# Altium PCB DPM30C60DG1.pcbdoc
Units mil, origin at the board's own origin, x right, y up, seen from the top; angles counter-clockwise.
Board outline 2020 x 1717.48 mil, 2 copper layers (Top Layer, Bottom Layer), stack 0 mil thick; 1 components, 0 nets, 24 pads, 0 vias.
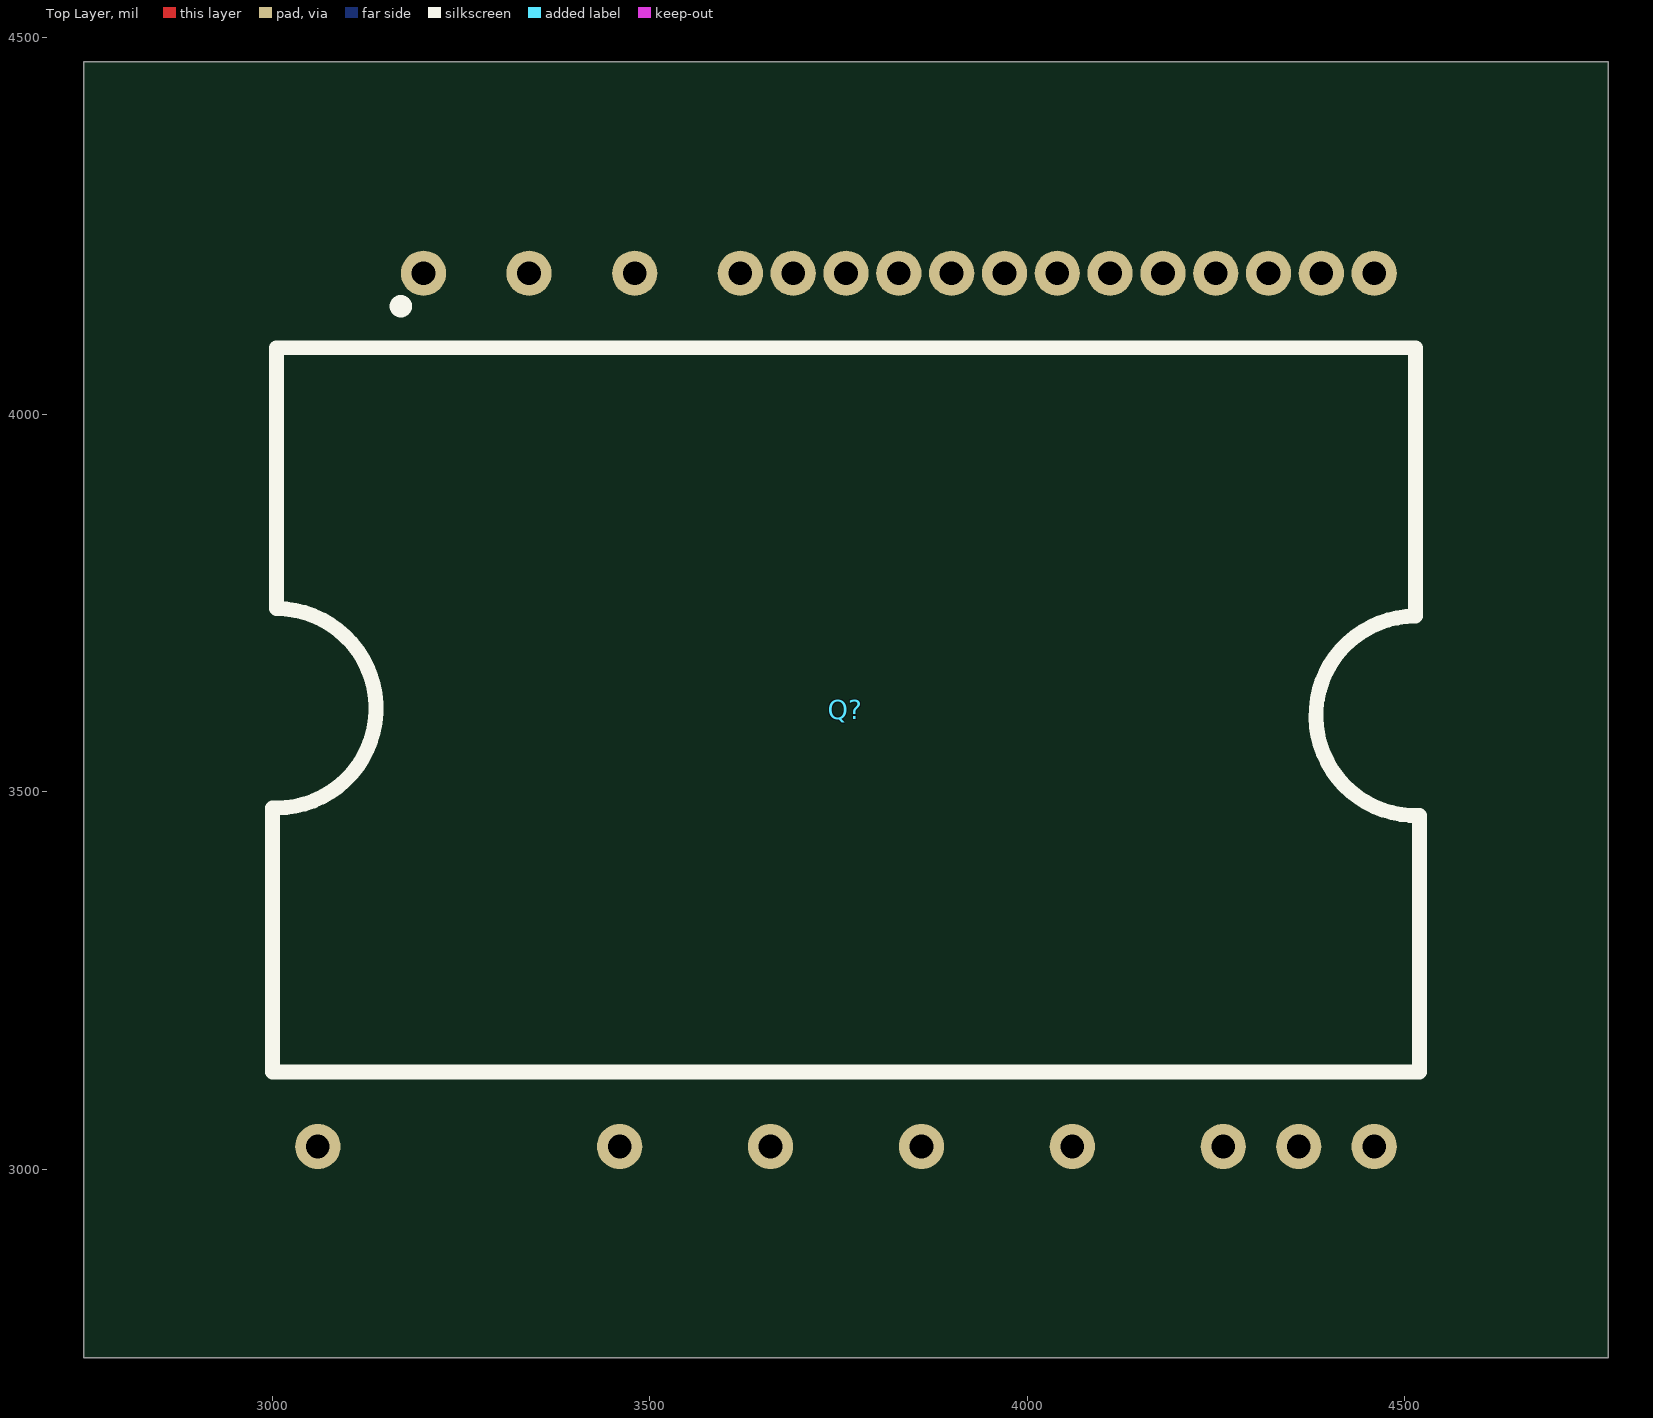
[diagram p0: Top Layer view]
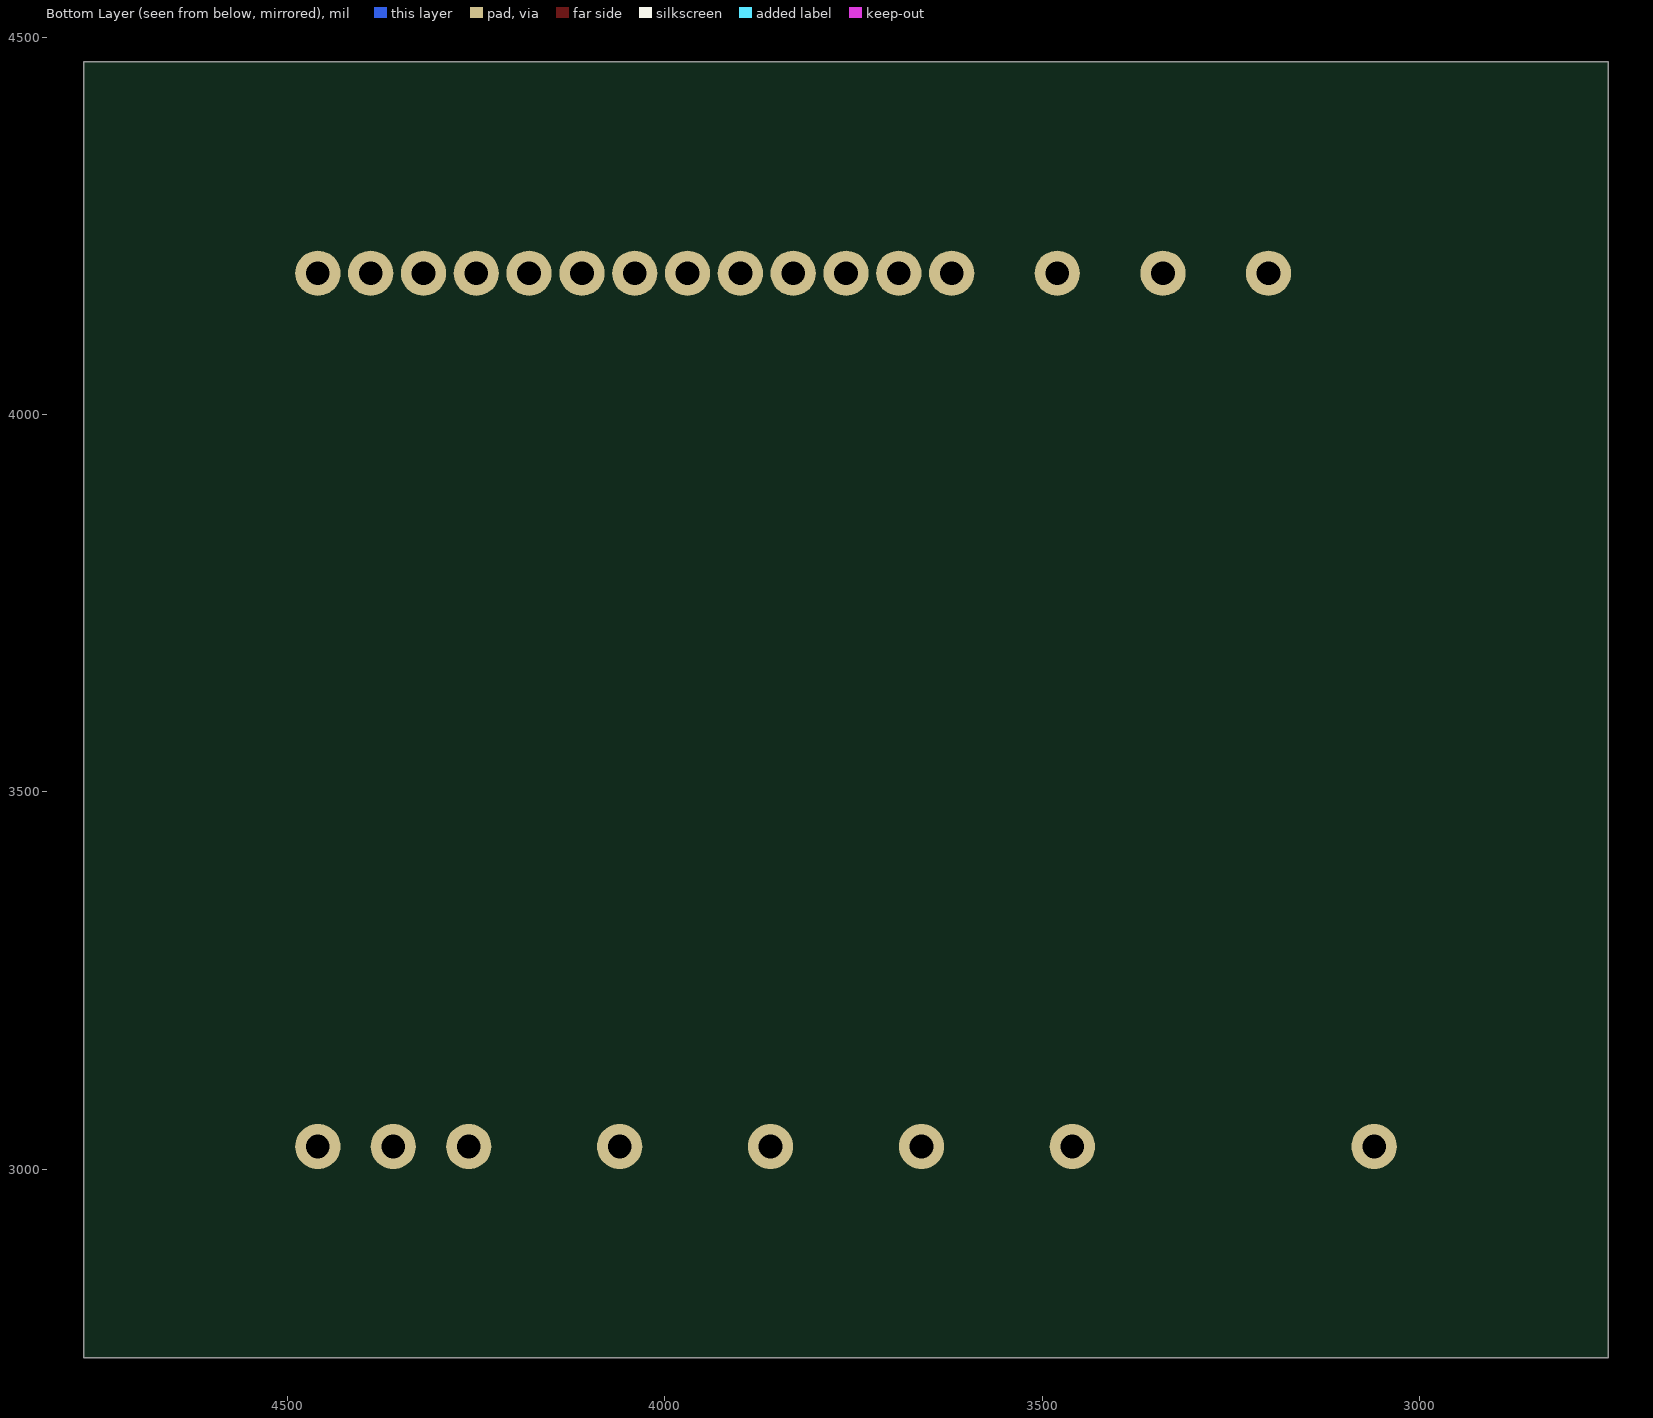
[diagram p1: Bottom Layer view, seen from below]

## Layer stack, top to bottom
Top Layer: signal copper (thickness not stored)
Bottom Layer: signal copper (thickness not stored)

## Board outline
4770,2750 2750,2750 2750,4467.48 4770,4467.48

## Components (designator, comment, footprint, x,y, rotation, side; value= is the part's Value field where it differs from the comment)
Q? "DPM30C60DG1" DIP-24_L38.0-W24.0-SPE30S60F-E 3760,3608.74 r0 top

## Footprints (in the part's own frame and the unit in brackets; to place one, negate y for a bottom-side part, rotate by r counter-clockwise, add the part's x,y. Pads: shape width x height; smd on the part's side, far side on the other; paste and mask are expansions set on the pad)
DIP-24_L38.0-W24.0-SPE30S60F-E [mil]
  round 60 hole 31.5 paste+0 mask+2.01: 2(-560,578.74) 3(-420,578.74) 4(-280,578.74) 5(-140,578.74) 6(-70,578.74) 7(0,578.74) 8(70,578.74) 9(140,578.74) 10(210,578.74) 11(280,578.74) 12(350,578.74) 13(420,578.74) 14(490,578.74) 15(559.99,578.74) 16(629.99,578.74) 17(700,578.74) 18(699.99,-578.74) 19(600,-578.74) 20(500,-578.74) 21(300,-578.74) 22(100,-578.74) 23(-100,-578.74) 24(-300,-578.74) 25(-700,-578.74)
  silkscreen extent -760,-480 760,540

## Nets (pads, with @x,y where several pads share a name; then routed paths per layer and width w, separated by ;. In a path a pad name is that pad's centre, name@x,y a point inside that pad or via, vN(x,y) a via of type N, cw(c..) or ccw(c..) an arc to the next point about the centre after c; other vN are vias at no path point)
pads on no net: Q?.2 Q?.3 Q?.4 Q?.5 Q?.6 Q?.7 Q?.8 Q?.9 Q?.10 Q?.11 Q?.12 Q?.13 Q?.14 Q?.15 Q?.16 Q?.17 Q?.18 Q?.19 Q?.20 Q?.21 Q?.22 Q?.23 Q?.24 Q?.25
